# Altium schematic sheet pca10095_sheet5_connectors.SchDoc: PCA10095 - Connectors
size A3; Organization: Nordic Semiconductor; DocumentNumber: 5; SheetNumber: 5; SheetTotal: 6; CompanyName: Nordic Semiconductor
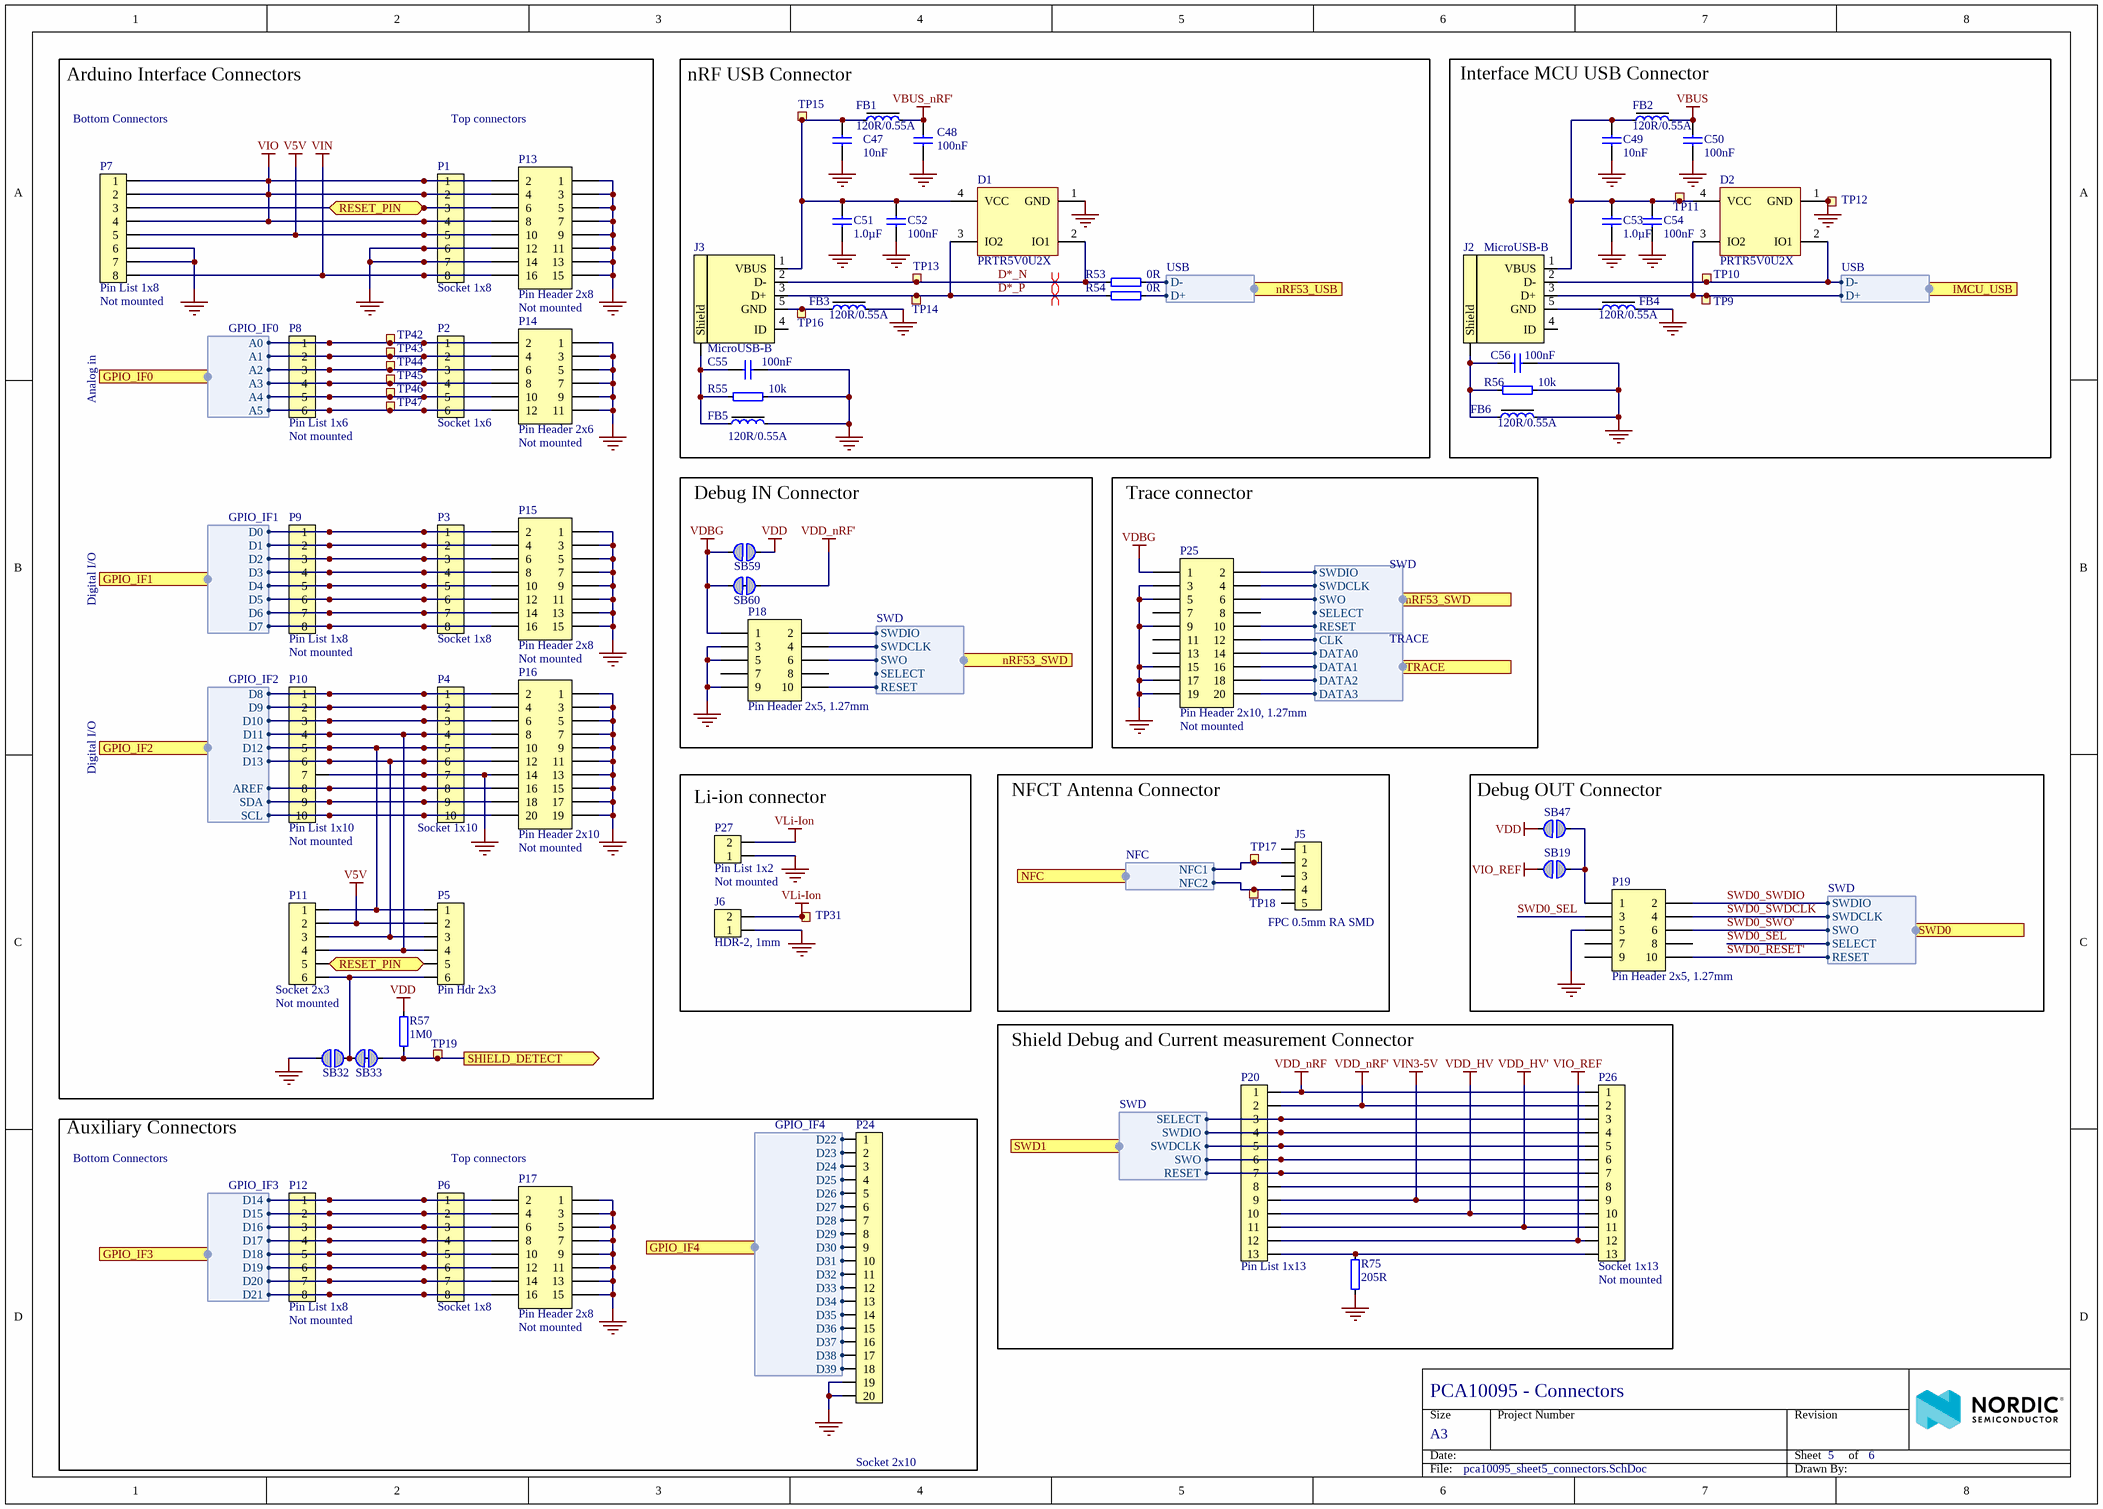
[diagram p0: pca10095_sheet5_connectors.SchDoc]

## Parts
C47  10nF  [CAPC0603X03L_C]
C48  100nF  [CAPC0603X03L_C]
C49  10nF  [CAPC0603X03L_C]
C50  100nF  [CAPC0603X03L_C]
C51  1.0µF  [CAPC1608X06L]
C52  100nF  [CAPC0603X03L_C]
C53  1.0µF  [CAPC1608X06L]
C54  100nF  [CAPC0603X03L_C]
C55  100nF  [CAPC0603X03L_C]
C56  100nF  [CAPC0603X03L_C]
D1  PRTR5V0U2X  [SOT190P230X110-4L]
D2  PRTR5V0U2X  [SOT190P230X110-4L]
FB1  120R/0.55A  [INDC1005X04L]
FB2  120R/0.55A  [INDC1005X04L]
FB3  120R/0.55A  [INDC1005X04L]
FB4  120R/0.55A  [INDC1005X04L]
FB5  120R/0.55A  [INDC1005X04L]
FB6  120R/0.55A  [INDC1005X04L]
J2  MicroUSB-B  [USB-Micro-B-RA-SMD-PiP]
J3  MicroUSB-B  [USB-Micro-B-RA-SMD-PiP]
J5  FPC 0.5mm RA SMD  [FPC_05P-0.5mm-RA-SMD]
J6  HDR-2, 1mm  [SM02B-SRSS-TB]
P1  Socket 1x8  [SOCKET_1x8_SMD]
P2  Socket 1x6  [SOCKET_1x6_SMD]
P3  Socket 1x8  [SOCKET_1x8_SMD]
P4  Socket 1x10  [SOCKET_1x10_SMD]
P5  Pin Hdr 2x3  [HDR_2x3-SMD]
P6  Socket 1x8  [SOCKET_1x8_SMD]
P7  Pin List 1x8  Assembly: Not mounted  [LIST_1x8_SMD-NC]
P8  Pin List 1x6  Assembly: Not mounted  [LIST_1x6_SMD-NC]
P9  Pin List 1x8  Assembly: Not mounted  [LIST_1x8_SMD-NC]
P10  Pin List 1x10  Assembly: Not mounted  [LIST_1x10_SMD-NC]
P11  Socket 2x3  Assembly: Not mounted  [SOCKET_2x3_SMD-2.54mm-bottom-NC]
P12  Pin List 1x8  Assembly: Not mounted  [LIST_1x8_SMD-NC]
P13  Pin Header 2x8  Assembly: Not mounted  [HDR_2x8-NC]
P14  Pin Header 2x6  Assembly: Not mounted  [HDR_2x6-NC]
P15  Pin Header 2x8  Assembly: Not mounted  [HDR_2x8-NC]
P16  Pin Header 2x10  Assembly: Not mounted  [HDR_2x10-NC]
P17  Pin Header 2x8  Assembly: Not mounted  [HDR_2x8-NC]
P18  Pin Header 2x5, 1.27mm  [HDR_2x5-SMD-1.27mm-K]
P19  Pin Header 2x5, 1.27mm  [HDR_2x5-SMD-1.27mm-K]
P20  Pin List 1x13  [LIST_1x13_SMD]
P24  Socket 2x10  [SOCKET_2x10_SMD-2.54mm]
P25  Pin Header 2x10, 1.27mm  Assembly: Not mounted  [HDR_2x10-SMD-1.27mm-NC]
P26  Socket 1x13  Assembly: Not mounted  [LIST_1x13_SMD-NC]
P27  Pin List 1x2  Assembly: Not mounted  [LIST_1x2-NC]
R53  0R  [RESC0603X03L_C]
R54  0R  [RESC0603X03L_C]
R55  10k  [RESC0603X03L_C]
R56  10k  [RESC0603X03L_C]
R57  1M0  [RESC0603X03L_C]
R75  205R  [RESC0603X03L_C]
SB19  Solderbridge  [Solderbridge]  (value not drawn)  (no BOM)
SB32  Solderbridge  [Solderbridge]  (value not drawn)  (no BOM)
SB33  Solderbridge  [Solderbridge_Shorted]  (value not drawn)  (net tie, no BOM)
SB47  Solderbridge  [Solderbridge]  (value not drawn)  (no BOM)
SB59  Solderbridge  [Solderbridge]  (value not drawn)  (no BOM)
SB60  Solderbridge  [Solderbridge_Shorted]  (value not drawn)  (net tie, no BOM)
TP9  Ø1.5mm,SMD  [TP_SMD_Ø1.5mm]  (value not drawn)  (no BOM)
TP10  Ø1.5mm,SMD  [TP_SMD_Ø1.5mm]  (value not drawn)  (no BOM)
TP11  Ø1.5mm,SMD  [TP_SMD_Ø1.5mm]  (value not drawn)  (no BOM)
TP12  Ø1.5mm,SMD  [TP_SMD_Ø1.5mm]  (value not drawn)  (no BOM)
TP13  Ø1.5mm,SMD  [TP_SMD_Ø1.5mm]  (value not drawn)  (no BOM)
TP14  Ø1.5mm,SMD  [TP_SMD_Ø1.5mm]  (value not drawn)  (no BOM)
TP15  Ø1.5mm,SMD  [TP_SMD_Ø1.5mm]  (value not drawn)  (no BOM)
TP16  Ø1.5mm,SMD  [TP_SMD_Ø1.5mm]  (value not drawn)  (no BOM)
TP17  Ø1.5mm,SMD  [TP_SMD_Ø1.5mm]  (value not drawn)  (no BOM)
TP18  Ø1.5mm,SMD  [TP_SMD_Ø1.5mm]  (value not drawn)  (no BOM)
TP19  Ø1.0mm,SMD  [TP_SMD_Ø1.0mm]  (value not drawn)  (no BOM)
TP31  Ø1.5mm,SMD  [TP_SMD_Ø1.5mm]  (value not drawn)  (no BOM)
TP42  Ø1.5mm,SMD  [TP_SMD_Ø1.5mm]  (value not drawn)  (no BOM)
TP43  Ø1.5mm,SMD  [TP_SMD_Ø1.5mm]  (value not drawn)  (no BOM)
TP44  Ø1.5mm,SMD  [TP_SMD_Ø1.5mm]  (value not drawn)  (no BOM)
TP45  Ø1.5mm,SMD  [TP_SMD_Ø1.5mm]  (value not drawn)  (no BOM)
TP46  Ø1.5mm,SMD  [TP_SMD_Ø1.5mm]  (value not drawn)  (no BOM)
TP47  Ø1.5mm,SMD  [TP_SMD_Ø1.5mm]  (value not drawn)  (no BOM)

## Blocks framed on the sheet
Arduino Interface Connectors: P1-P5 P7-P11 P13-P16 R57 SB32 SB33 TP19 TP42-TP47
nRF USB Connector: C47 C48 C51 C52 C55 D1 FB1 FB3 FB5 J3 R53-R55 TP13-TP16
Interface MCU USB Connector: C49 C50 C53 C54 C56 D2 FB2 FB4 FB6 J2 R56 TP9-TP12
Debug IN Connector: P18 SB59 SB60
Trace connector: P25
Li-ion connector: J6 P27 TP31
NFCT Antenna Connector: J5 TP17 TP18
Debug OUT Connector: P19 SB19 SB47
Shield Debug and Current measurement Connector: P20 P26 R75
Auxiliary Connectors: P6 P12 P17 P24

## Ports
GPIO_IF0 (harness GPIO_IF0), GPIO_IF1 (harness GPIO_IF1), GPIO_IF2 (harness GPIO_IF2), GPIO_IF3 (harness GPIO_IF3), GPIO_IF4 (harness GPIO_IF4), IMCU_USB (harness USB), NFC (harness NFC), nRF53_SWD (harness SWD), nRF53_USB (harness USB), RESET_PIN (bidir), SHIELD_DETECT (out), SWD0 (harness SWD), SWD1 (harness SWD), TRACE (harness TRACE)

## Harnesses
USB: D+, D-
SWD: SWDIO, SWDCLK, SWO, RESET, SELECT
TRACE: CLK, DATA0, DATA1, DATA3, DATA2
NFC: NFC2, NFC1
GPIO_IF0: A0, A1, A2, A3, A4, A5
GPIO_IF1: D0, D1, D2, D3, D4, D5, D6, D7
GPIO_IF2: D8, D9, D10, D11, D12, D13, AREF, SDA, SCL
GPIO_IF3: D14, D15, D16, D17, D18, D19, D20, D21
GPIO_IF4: D22, D23, D24, D25, D26, D27, D28, D29, D30, D31, D32, D33, D34, D35, D36, D37, D38, D39

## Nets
GND: C47.1 C48.1 C49.2 C50.1 C51.1 C52.1 C53.1 C54.1 C55.1 C56.1 D1.1(GND) D2.1(GND) FB3.2 FB4.2 FB5.2 FB6.2 J6.1 P1.6 P1.7 P4.7 P7.6 P7.7 P10.7 P13.1 P13.3 P13.5 P13.7 P13.9 P13.11 P13.12 P13.13 P13.14 P13.15 P14.1 P14.3 P14.5 P14.7 P14.9 P14.11 P15.1 P15.3 P15.5 P15.7 P15.9 P15.11 P15.13 P15.15 P16.1 P16.3 P16.5 P16.7 P16.9 P16.11 P16.13 P16.14 P16.15 P16.17 P16.19 P17.1 P17.3 P17.5 P17.7 P17.9 P17.11 P17.13 P17.15 P18.3 P18.5 P18.9 P19.5 P24.19 P24.20 P25.3 P25.5 P25.9 P25.15 P25.17 P25.19 P27.1 R55.1 R56.1 R75.1 SB32.1 TP12.1
V5V: P1.5 P5.2 P7.5 P11.2 P13.10
VBUS: C50.2 FB2.2
VBUS_nRF': C48.2 FB1.2
VDBG: P18.1 P25.1 SB59.1 SB60.1
VDD: R57.2 SB47.1 SB59.2
VDD_HV: P20.10 P26.10
VDD_HV': P20.11 P26.11
VDD_nRF: P20.1 P26.1
VDD_nRF': P20.2 P26.2 SB60.2
VIN: P1.8 P7.8 P13.16
VIN3-5V: P20.9 P26.9
VIO: P1.1 P1.2 P1.4 P7.1 P7.2 P7.4 P13.2 P13.4 P13.8
VIO_REF: P20.12 P26.12 SB19.1
VLi-Ion: J6.2 P27.2 TP31.1
D*_N: D1.2(IO1) J3.2(D-) R53.2 TP13.1
D*_P: D1.3(IO2) J3.3(D+) R54.2 TP14.1
RESET_PIN: P1.3 P5.5 P7.3 P11.5 P13.6 ; port RESET_PIN
SHIELD_DETECT: R57.1 SB33.2 TP19.1 ; port SHIELD_DETECT
SWD0_RESET': P19.10 ; port SWD0.RESET
SWD0_SEL: P19.3 ; port SWD0.SELECT
SWD0_SWDCLK: P19.4 ; port SWD0.SWDCLK
SWD0_SWDIO: P19.2 ; port SWD0.SWDIO
SWD0_SWO': P19.6 ; port SWD0.SWO
NetC47_2: C47.2 C51.2 C52.2 D1.4(VCC) FB1.1 J3.1(VBUS) TP15.1
NetC49_1: C49.1 C53.2 C54.2 D2.4(VCC) FB2.1 J2.1(VBUS) TP11.1
NetC55_2: C55.2 FB5.1 J3.6(Shield) R55.2
NetC56_2: C56.2 FB6.1 J2.6(Shield) R56.2
NetD2_2: D2.2(IO1) J2.2(D-) TP10.1 ; port IMCU_USB.D-
NetD2_3: D2.3(IO2) J2.3(D+) TP9.1 ; port IMCU_USB.D+
NetFB3_1: FB3.1 J3.5(GND) TP16.1
NetFB4_1: FB4.1 J2.5(GND)
NetJ5_2: J5.2 TP17.1 ; port NFC.NFC1
NetJ5_4: J5.4 TP18.1 ; port NFC.NFC2
NetP2_1: P2.1 P8.1 P14.2 TP42.1 ; port GPIO_IF0.A0
NetP2_2: P2.2 P8.2 P14.4 TP43.1 ; port GPIO_IF0.A1
NetP2_3: P2.3 P8.3 P14.6 TP44.1 ; port GPIO_IF0.A2
NetP2_4: P2.4 P8.4 P14.8 TP45.1 ; port GPIO_IF0.A3
NetP2_5: P2.5 P8.5 P14.10 TP46.1 ; port GPIO_IF0.A4
NetP2_6: P2.6 P8.6 P14.12 TP47.1 ; port GPIO_IF0.A5
NetP3_1: P3.1 P9.1 P15.2 ; port GPIO_IF1.D0
NetP3_2: P3.2 P9.2 P15.4 ; port GPIO_IF1.D1
NetP3_3: P3.3 P9.3 P15.6 ; port GPIO_IF1.D2
NetP3_4: P3.4 P9.4 P15.8 ; port GPIO_IF1.D3
NetP3_5: P3.5 P9.5 P15.10 ; port GPIO_IF1.D4
NetP3_6: P3.6 P9.6 P15.12 ; port GPIO_IF1.D5
NetP3_7: P3.7 P9.7 P15.14 ; port GPIO_IF1.D6
NetP3_8: P3.8 P9.8 P15.16 ; port GPIO_IF1.D7
NetP4_1: P4.1 P10.1 P16.2 ; port GPIO_IF2.D8
NetP4_2: P4.2 P10.2 P16.4 ; port GPIO_IF2.D9
NetP4_3: P4.3 P10.3 P16.6 ; port GPIO_IF2.D10
NetP4_4: P4.4 P5.4 P10.4 P11.4 P16.8 ; port GPIO_IF2.D11
NetP4_5: P4.5 P5.1 P10.5 P11.1 P16.10 ; port GPIO_IF2.D12
NetP4_6: P4.6 P5.3 P10.6 P11.3 P16.12 ; port GPIO_IF2.D13
NetP4_8: P4.8 P10.8 P16.16 ; port GPIO_IF2.AREF
NetP4_9: P4.9 P10.9 P16.18 ; port GPIO_IF2.SDA
NetP4_10: P4.10 P10.10 P16.20 ; port GPIO_IF2.SCL
NetP5_6: P5.6 P11.6 SB32.2 SB33.1
NetP6_1: P6.1 P12.1 P17.2 ; port GPIO_IF3.D14
NetP6_2: P6.2 P12.2 P17.4 ; port GPIO_IF3.D15
NetP6_3: P6.3 P12.3 P17.6 ; port GPIO_IF3.D16
NetP6_4: P6.4 P12.4 P17.8 ; port GPIO_IF3.D17
NetP6_5: P6.5 P12.5 P17.10 ; port GPIO_IF3.D18
NetP6_6: P6.6 P12.6 P17.12 ; port GPIO_IF3.D19
NetP6_7: P6.7 P12.7 P17.14 ; port GPIO_IF3.D20
NetP6_8: P6.8 P12.8 P17.16 ; port GPIO_IF3.D21
NetP18_2: P18.2 P25.2 ; port nRF53_SWD.SWDIO
NetP18_4: P18.4 P25.4 ; port nRF53_SWD.SWDCLK
NetP18_6: P18.6 P25.6 ; port nRF53_SWD.SWO
NetP18_10: P18.10 P25.10 ; port nRF53_SWD.RESET
NetP19_1: P19.1 SB19.2 SB47.2
NetP20_3: P20.3 P26.3 ; port SWD1.SELECT
NetP20_4: P20.4 P26.4 ; port SWD1.SWDIO
NetP20_5: P20.5 P26.5 ; port SWD1.SWDCLK
NetP20_6: P20.6 P26.6 ; port SWD1.SWO
NetP20_7: P20.7 P26.7 ; port SWD1.RESET
NetP20_8: P20.8 P26.8
NetP20_13: P20.13 P26.13 R75.2
NetP24_1: P24.1 ; port GPIO_IF4.D22
NetP24_2: P24.2 ; port GPIO_IF4.D23
NetP24_3: P24.3 ; port GPIO_IF4.D24
NetP24_4: P24.4 ; port GPIO_IF4.D25
NetP24_5: P24.5 ; port GPIO_IF4.D26
NetP24_6: P24.6 ; port GPIO_IF4.D27
NetP24_7: P24.7 ; port GPIO_IF4.D28
NetP24_8: P24.8 ; port GPIO_IF4.D29
NetP24_9: P24.9 ; port GPIO_IF4.D30
NetP24_10: P24.10 ; port GPIO_IF4.D31
NetP24_11: P24.11 ; port GPIO_IF4.D32
NetP24_12: P24.12 ; port GPIO_IF4.D33
NetP24_13: P24.13 ; port GPIO_IF4.D34
NetP24_14: P24.14 ; port GPIO_IF4.D35
NetP24_15: P24.15 ; port GPIO_IF4.D36
NetP24_16: P24.16 ; port GPIO_IF4.D37
NetP24_17: P24.17 ; port GPIO_IF4.D38
NetP24_18: P24.18 ; port GPIO_IF4.D39
NetP25_12: P25.12 ; port TRACE.CLK
NetP25_14: P25.14 ; port TRACE.DATA0
NetP25_16: P25.16 ; port TRACE.DATA1
NetP25_18: P25.18 ; port TRACE.DATA2
NetP25_20: P25.20 ; port TRACE.DATA3
NetR53_1: R53.1 ; port nRF53_USB.D-
NetR54_1: R54.1 ; port nRF53_USB.D+

Not connected (* = marked no-connect by the designer): J2 4(ID); J3 4(ID); J5 1 3 5; P18 7 8; P19 7 8 9; P25 7 8 11 13

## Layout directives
differential pair: D*_N, D*_P

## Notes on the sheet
- Bottom Connectors
- Top connectors
- Analog in
- Digital I/O

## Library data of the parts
C47 C49 = C0201-10n: Capacitor, X7R, ±10%; Manufacturer: N.A.; Part number IPS: 00000003480; Note: 10V; Pad Count: 2
C48 C50 C52 C54-C56 = C0201-100n: Capacitor, X5R, ±10%; Manufacturer: N.A.; Part number IPS: 00000001248, 00000002505; Note: 16V; Pad Count: 2
C51 C53 = C0603-1µ0: Capacitor, X7R, ±10%; Manufacturer: N.A.; Part number IPS: 00000000616; Note: 16V; Artikkelnr Noca: 20039282; Pad Count: 2
D1 D2 = PRTR5V0U2X: Ultra low capacitance double rail-to-rail ESD protection diode; Manufacturer: NXP Semiconductors; Part number IPS: 00000009951; Note: N.A.; Artikkelnr Noca: 10069015; Pad Count: 4
FB1-FB6 = FB0402-120R@100M-500mA: Ferrite Bead, 120 Ohm @ 100MHz, 500mA, 250 mOhm Max; Manufacturer: Murata; Manufacturer Part Number: BLM15AG121SN1D; Part number IPS: 00000009954; Note: Chip EMIFIL Inductor Type Chip Ferrite Bead; Artikkelnr Noca: 33029317; Pad Count: 2
J2 J3 = USB-Micro-B-RA-SMD-PiP: MicroUSB-B-SMT; Manufacturer: Allen Creations Corp.; Manufacturer Part Number: AJU55-BS2111-L; Part number IPS: 00000007790; Note: N.A.; Artikkelnr Noca: 55029020; Pad Count: 5
J5 = FPC_05P-0.5mm-RA-SMD: 0.5mm FPC, 5P,Right Angle SMT,Double Contact,H=1.2mm,White, Tin plated; Manufacturer: W-CON; Manufacturer Part Number: 5141-05RZDNWR01; Part number IPS: 00000007792; Note: N.A.; Artikkelnr Noca: 55010020; Pad Count: 7
J6 = SM02B-SRSS-TB: 1.0mm pitch connector side entry SMD; Manufacturer: JST Sales America Inc.; Manufacturer Part Number: SM02B-SRSS-TB(LF)(SN); Part number IPS: 00000007791; Note: JST, Header; Artikkelnr Noca: 55010030; Pad Count: 2
P1 P3 P6 = Socket 1x8 SMD: Socket 1x8, 2.54mm (100mil), SMD; Manufacturer: W-CON; Manufacturer Part Number: 2171-108MS0CUNR1; Part number IPS: 00000009963; Note: N.A.; Artikkelnr Noca: 55030002; Pad Count: 8
P2 = Socket 1x6 SMD: Socket 1x6, 2.54mm (100mil), SMD; Manufacturer: W-CON; Manufacturer Part Number: 2171-106MS0CUNR1; Part number IPS: 00000009964; Note: N.A.; Artikkelnr Noca: 55030001; Pad Count: 6
P4 = Socket 1x10 SMD: Socket 1x10, 2.54mm (100mil), SMD; Manufacturer: W-CON; Manufacturer Part Number: 2171-110MS0CUNR1; Part number IPS: 00000009965; Note: N.A.; Artikkelnr Noca: 55030004; Pad Count: 10
P5 = Pin Header 2x3 SMD: Pin Header 2x3, 2.54mm (100mil) SMD; Manufacturer: W-CON; Manufacturer Part Number: 1125-1203S0M116R1; Part number IPS: 00000009966; Artikkelnr Noca: 55010007; Pad Count: 6
P7 P9 P12 = Pin List 1x8 SMD, N.C.: Pin List 1x8, 2.54mm (100mil), SMD; Manufacturer: W-CON; Manufacturer Part Number: 1125-1108S0M116R2; Note: N.A.; Artikkelnr Noca: 55010006; Pad Count: 8
P8 = Pin List 1x6 SMD, N.C.: Pin List 1x6, 2.54mm (100mil), SMD; Manufacturer: W-CON; Manufacturer Part Number: 1125-1106S0M116R2; Note: N.A.; Artikkelnr Noca: 55010026; Pad Count: 6
P10 = Pin List 1x10 SMD, N.C.: Pin List 1x10, 2.54mm (100mil), SMD; Manufacturer: W-CON; Manufacturer Part Number: 1125-1110S0M116R2; Note: N.A.; Artikkelnr Noca: 55010028; Pad Count: 10
P11 = Socket 2x3 SMD Bottom, N.C.: Socket 2x3, 2.54mm (100mil), SMD; Manufacturer: W-CON; Manufacturer Part Number: 2171-203MS0CUNR1; Note: N.A.; Artikkelnr Noca: 55030010; Pad Count: 6
P13 P15 P17 = Pin Header 2x8, N.C.: Pin Header 2x8, 2.54mm (100mil); Manufacturer: N.A.; Pad Count: 16
P14 = Pin Header 2x6, N.C.: Pin Header 2x6, 2.54mm (100mil); Manufacturer: N.A.; Pad Count: 12
P16 = Pin Header 2x10, N.C.: Pin Header 2x10, 2.54mm (100mil); Manufacturer: N.A.; Pad Count: 20
P18 P19 = Pin Header 2x5 SMD, 1.27mm, KS: Pin Header 2x5, 1.27mm (50mil), SMD, Keying Shroud; Manufacturer: W-CON; Manufacturer Part Number: 3132-10MS0BK00R1; Part number IPS: 00000009968; Note: N.A.; Artikkelnr Noca: 55010009; Pad Count: 10
P20 = Pin List 1x13 SMD: Pin List 1x13, 2.54mm (100mil), SMD; Manufacturer: N.A.; Part number IPS: 00000002499; Pad Count: 13
P24 = Socket 2x10 SMD: Socket 2x10, 2.54mm (100mil), SMD; Manufacturer: W-CON; Manufacturer Part Number: 2171-210MS0CUNR1; Note: N.A.; Pad Count: 20
P25 = Pin Header 2x10 SMD, 1.27mm, KS, N.C.: Pin Header 2x10, 1.27mm (50mil), SMD, Keying Shroud; Manufacturer: W-CON; Manufacturer Part Number: 3132-20MS0BK00R1; Note: N.A.; Pad Count: 20
P26 = Socket 1x13 SMD, N.C.: Socket 1x13, 2.54mm (100mil), SMD; Manufacturer: W-CON; Manufacturer Part Number: 2171-113MS0CUNR1; Note: N.A.; Pad Count: 13
P27 = Pin List 1x2, N.C.: Pin List 1x2, 2.54mm (100mil); Manufacturer: N.A.; Pad Count: 2
R53 R54 = R0201-0R: Resistor, ±5%, 0.05W; Manufacturer: N.A.; Part number IPS: 00000003245; Note: Chip Res 5%; Pad Count: 2
R55 R56 = R0201-10k: Resistor, ±1%, 0.05W; Manufacturer: N.A.; Part number IPS: 00000001255; Note: Chip Res 1%; Pad Count: 2
R57 = R0201-1M0: Resistor, ±1%, 0.05W; Manufacturer: N.A.; Part number IPS: 00000001418; Note: Chip Res 1%; Pad Count: 2
R75 = R0201-205: Resistor, ±1%, 0.05W; Manufacturer: N.A.; Note: Chip Res 1%; Pad Count: 2
SB19 SB32 SB47 SB59 = Solderbridge: Manufacturer: N.A.; Pad Count: 2
SB33 SB60 = Solderbridge Shorted: Shorted Solderbridge; Manufacturer: N.A.; Pad Count: 2
TP9-TP18 TP31 TP42-TP47 = TP_SMD_Ø1.5MM: 1.5mm circular SMD testpad; Manufacturer: Nordic Semiconductor; Manufacturer Part Number: N.A.; Pad Count: 1
TP19 = TP_SMD_Ø1.0MM: 1.0mm circular SMD testpad; Manufacturer: Nordic Semiconductor; Manufacturer Part Number: N.A.; Pad Count: 1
